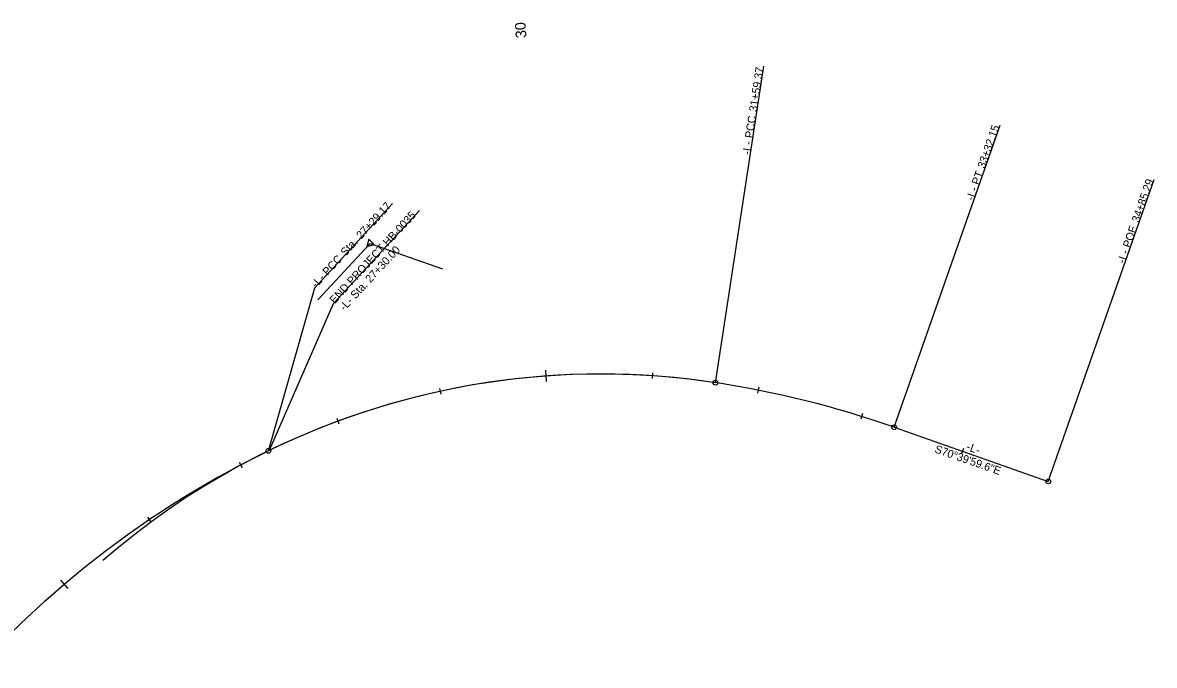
# Model space of a CAD drawing. Extents: x 1768031 to 1770464, y 999587 to 1004918.
# Drawn here: x 1769132 to 1770192, y 1000374 to 1000977 of the extents above; entities that cross this region are included whole.
import ezdxf

# ---------------------------------------------------------------- set-up
doc = ezdxf.new("R2010")
doc.units = 0
for name, color, linetype in [('Default', 7, 'Continuous'), ('P_NCDOT_SS_Fill_Text', 7, 'Continuous'), ('P_RDY_DGN_Element_Guardrail', 7, 'Continuous'), ('P_RDY_Dimension', 7, 'Continuous'), ('P_RDY_Dimension_Text', 7, 'Continuous'), ('P_RDY_DSN_Text', 7, 'Continuous'), ('P_RDY_Limits_of_Construction', 7, 'Continuous'), ('P_RDY_Slope_Stake_Cut_Text', 7, 'Continuous'), ('P_RDY_Terminator_Cell', 7, 'Continuous'), ('Typical_Arrow_Superelevation_CELL', 7, 'Continuous')]:
    doc.layers.add(name, color=color, linetype=linetype)

msp = doc.modelspace()

# ---------------------------------------------------------------- linework, layer by layer
at = {"layer": 'Default'}
for q in [(1769408.7, 1000716.7), (1769525.5, 1000745.8), (1769457.6, 1000769.6)]:
    msp.add_line((1769457.6, 1000769.6), q, dxfattribs=at)
msp.add_lwpolyline([(1769456.5, 1000773.6), (1769454.6, 1000766.7), (1769461.6, 1000768.5)], close=True, dxfattribs=at)
at = {"layer": 'P_RDY_DGN_Element_Guardrail'}
for centre in [(1769622.3, 1000645.4), (1769362.4, 1000575.2)]:
    msp.add_circle(centre, 0.05, dxfattribs=at)
at = {"layer": 'P_RDY_Dimension'}
for p, q in [((1769621.9, 1000650.7), (1769622.7, 1000640.1)), ((1769167.7, 1000454.1), (1769174.6, 1000446.1))]:
    msp.add_line(p, q, dxfattribs=at)
at = {"layer": 'P_RDY_DSN_Text'}
msp.add_line((1769948.6, 1000597.3), (1770093.1, 1000546.6), dxfattribs=at)
for centre, radius, start, end in [((1769674, 999937.2), 710, 81.3113, 116.0279), ((1769640.7, 999719.8), 930, 70.6666, 81.3113), ((1769763.9, 999753), 915, 116.0279, 137.2512)]:
    msp.add_arc(centre, radius, start, end, dxfattribs=at)
at = {"layer": 'P_RDY_Limits_of_Construction'}
msp.add_arc((1769763.9, 999753), 915, 116.0279, 137.2512, dxfattribs=at)
at = {"layer": 'P_RDY_Slope_Stake_Cut_Text'}
for p, q in [((1769781.2, 1000639.1), (1769826.5, 1000935.7)), ((1769948.6, 1000597.3), (1770047.9, 1000880.4)), ((1770093.1, 1000546.6), (1770192.4, 1000829.7)), ((1769405.8, 1000728.1), (1769478.7, 1000807)), ((1769423.2, 1000713.1), (1769503.9, 1000800.4)), ((1769362.4, 1000575.2), (1769405.8, 1000728.1)), ((1769423.2, 1000713.1), (1769363.2, 1000575.6))]:
    msp.add_line(p, q, dxfattribs=at)
for centre in [(1769781.2, 1000639.1), (1769948.6, 1000597.3), (1769362.4, 1000575.2), (1770093.1, 1000546.6)]:
    msp.add_circle(centre, 2.25, dxfattribs=at)
at = {"layer": 'P_RDY_Terminator_Cell'}
for p, q in [((1769722.4, 1000648.4), (1769722, 1000642.9)), ((1769522.8, 1000633.8), (1769524, 1000628.4)), ((1769821.8, 1000634.8), (1769820.7, 1000629.4)), ((1769426.5, 1000605.7), (1769428.5, 1000600.5)), ((1769918.9, 1000610.1), (1769917.3, 1000604.8)), ((1770013.6, 1000577.5), (1770011.7, 1000572.3)), ((1769335.1, 1000564.5), (1769337.7, 1000559.6)), ((1769249.2, 1000512.9), (1769252.3, 1000508.3))]:
    msp.add_line(p, q, dxfattribs=at)
at = {"layer": 'Typical_Arrow_Superelevation_CELL'}
msp.add_arc((1769674, 999937.2), 710, 81.3113, 131.0852, dxfattribs=at)

# ---------------------------------------------------------------- texts
at = {"layer": 'P_NCDOT_SS_Fill_Text'}
for s, p in [('S70°39\'59.6"E', (1769986, 1000573.9)), ('-', (1770015.7, 1000576.2)), ('L', (1770019, 1000575)), ('-', (1770024.5, 1000573.1))]:
    msp.add_text(s, height=7.5, rotation=340.6666, dxfattribs=at).set_placement(p)
at = {"layer": 'P_RDY_Dimension_Text'}
msp.add_text('30', height=10, rotation=94.1721, dxfattribs=at).set_placement((1769604.2, 1000962.5))
at = {"layer": 'P_RDY_Slope_Stake_Cut_Text'}
for s, rotation, p in [('31+59.37', 81.3113, (1769820, 1000892.7)), ('PCC', 81.3113, (1769816.2, 1000867.9)), ('33+32.15', 70.6666, (1770033.5, 1000839.3)), ('L', 81.3113, (1769814.3, 1000855.8)), ('- ', 81.3113, (1769815.2, 1000861.6)), ('-', 81.3113, (1769813.8, 1000852.4)), ('PT', 70.6666, (1770028.1, 1000823.9)), ('34+85.29', 70.6666, (1770178, 1000788.7)), ('L', 70.6666, (1770024.1, 1000812.4)), ('- ', 70.6666, (1770026, 1000817.9)), ('27+29.17', 47.2512, (1769449.4, 1000773.2)), ('-', 70.6666, (1770022.9, 1000809.1)), ('END PROJECT HB-0035', 47.2512, (1769424.4, 1000712.5)), ('POE', 70.6666, (1770169.7, 1000765)), (' Sta. ', 47.2512, (1769432.8, 1000755.2)), ('-L- Sta. 27+30.00', 47.2512, (1769433.7, 1000706)), ('PCC', 47.2512, (1769417.8, 1000739)), ('L', 70.6666, (1770165.7, 1000753.5)), ('-', 70.6666, (1770164.5, 1000750.2)), ('- ', 70.6666, (1770167.6, 1000759)), ('L', 47.2512, (1769409.5, 1000730)), ('- ', 47.2512, (1769413.5, 1000734.3)), ('-', 47.2512, (1769407.1, 1000727.4))]:
    msp.add_text(s, height=7.5, rotation=rotation, dxfattribs=at).set_placement(p)

doc.saveas('drawing.dxf')
